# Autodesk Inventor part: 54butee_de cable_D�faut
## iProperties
Created: 2011-01
Part Number: 54butee_de cable_D�faut
Document SubType Name: Modeling
Designer: eric
Density: 1 g/cm^3
Mass: 0.530405 g
Surface Area: 4.98383 cm^2
Volume: 0.530405 cm^3
Author: eric
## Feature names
1. Base1
